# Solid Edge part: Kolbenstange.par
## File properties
Username: bmolnar
Dokumentum tartalom típus: 0
Author: bmolnar
Last saved by: bmolnar
Revision: 84
Sűrűség: 0,000 kg/m^3
Pontosság: 0,990
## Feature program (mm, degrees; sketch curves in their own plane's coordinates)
base feature "unnamed BaseFeature 1"
sketch for "unnamed Protrusion 1" plane through (0, 0, -20.6) normal (0, 0, -1) x-axis (0, 1, 0)
  circle centre (0, 0) radius 16
extrude "unnamed Protrusion 1" add finite 7.9 along +normal
thread "unnamed Thread 1"
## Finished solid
Body 1: solid body, 17 faces, 23 edges, 8 vertices.
  Faces by surface: plane 8, cylinder 4, torus 3, cone 2
  Edges by curve: circle 13, line 6, ellipse 2, intersection 2
Bounding box of the edges (mm; curved faces can reach further): 32.000 x 32.000 x 107.500, from (-16, -16, -28.5) to (16, 16, 79).
Cylindrical faces by radius (mm): R3.95 x1, R5 x1, R6 x1, R16 x1
Conical faces (half-angle, radius in mm at the cone's reference point): 20 deg R4.5 x1, 60 deg R4.575 x1
Toroidal faces (ring radius, tube radius in mm): R4.35 r0.4 x2, R4.8 r1.2 x1
Planar faces by outward normal: +x 1, +z 3, -x 1, -z 1, oblique 2
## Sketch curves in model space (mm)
circle centre (0, 0, -20.6) radius 16
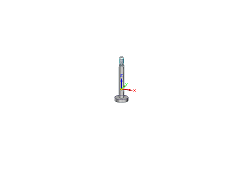
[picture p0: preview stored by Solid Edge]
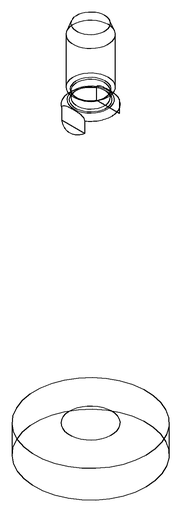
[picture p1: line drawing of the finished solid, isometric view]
